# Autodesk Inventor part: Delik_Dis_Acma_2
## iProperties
Company: Autodesk, Inc.
Created: 2004-06
Part Number: Delik_Dis_Acma_2
Document SubType Name: Modeling
Designer: Autodesk
Manufacturer: Standard
Standards Organization: Custom
Density: 1 g/cm^3
Author: Autodesk
Subject: Autodesk Inventor
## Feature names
1. Extrusion1
2. Extrusion2
3. Extrusion3
4. Extrusion4
5. Extrusion5
6. Fillet1
7. Circular Pattern1
8. Revolution1
9. Extrusion6
10. Extrusion7
11. Fillet2
12. Mirror1
13. Extrusion8
14. Hole1
15. Hole2
16. Hole3
17. Hole4
18. Hole5
19. Hole6
20. Hole7
21. Hole8
